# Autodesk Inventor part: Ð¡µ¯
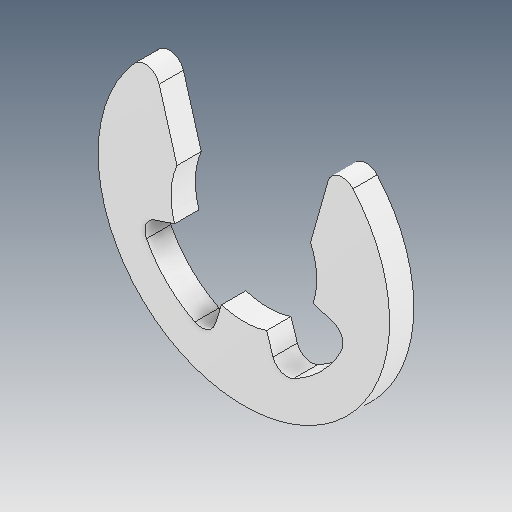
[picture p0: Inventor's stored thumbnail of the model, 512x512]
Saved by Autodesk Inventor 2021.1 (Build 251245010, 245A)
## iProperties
Created: 2021-05
Part Number: Ð¡µ¯
Material: Ogólny
Document SubType Name: Modeling
Designer: user
Density: 1 g/cm^3
Appearance: Domyślna
Author: user
Revision Number: ÈÎºÎ
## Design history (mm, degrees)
feature "ÊäÈë1"
node "Bryła1"
